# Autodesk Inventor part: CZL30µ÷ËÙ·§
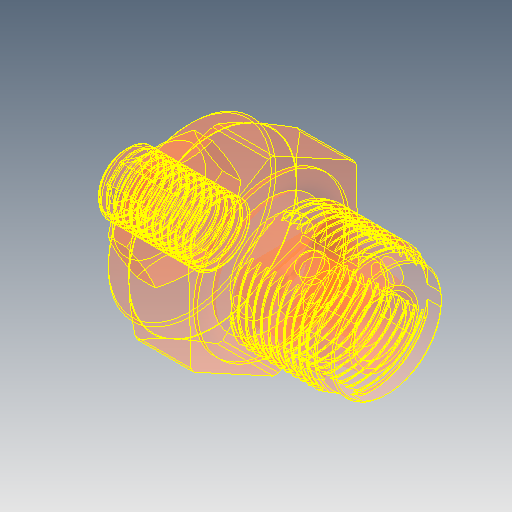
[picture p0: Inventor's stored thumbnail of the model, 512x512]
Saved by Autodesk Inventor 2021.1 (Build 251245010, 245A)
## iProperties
Created: 2021-05
Part Number: CZL30µ÷ËÙ·§
Material: Ogólny
Document SubType Name: Modeling
Designer: user
Density: 1 g/cm^3
Appearance: Domyślna
Author: user
Revision Number: ÈÎºÎ
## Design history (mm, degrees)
feature "Złożony1"
body "Srf1"
